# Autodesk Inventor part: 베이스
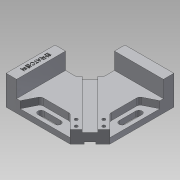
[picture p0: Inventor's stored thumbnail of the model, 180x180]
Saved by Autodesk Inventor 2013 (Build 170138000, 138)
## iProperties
Created: 2019-04
Part Number: 베이스
Material: 알루미늄 6061
Document SubType Name: Modeling
Designer: Administrator
Mass: 603.735 g
Surface Area: 426.536 cm^2
Volume: 222.78 cm^3
Density: 2.71 g/cm^3
Author: Administrator
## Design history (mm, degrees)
sketch "스케치1"
  geometry: L1 (60, -60)-(-60, -60); L2 (-60, -60)-(-60, 60); L3 (-60, 60)-(60, 60); L4 (60, 60)-(60, -60); L5 (60, -60)-(-60, 60); L6 (-60, -60)-(60, 60); 1 further point
  constraints: 12 end point, 2 midpoint, 2 parallel, 1 horizontal, 1 perpendicular
  dimensions: "d0" = 120 distance of L2.end L3.end; "d1" = 120 distance of L1.end L2.end
extrude "돌출1" new body sketch "스케치1" stored distance "d2" = 42; taper "d3" = 0 deg
sketch "스케치2"
  geometry: L1 (-60, -60)-(60, -60) reference; L2 (60, -60)-(60, 60) reference; L3 (60, 60)-(-60, 60) reference; L4 (-60, 60)-(-60, -60) reference; L5 (-45, 45)-(60, 45); L6 (-45, -60)-(-45, 45); L7 (-45, -60)-(60, -60); L8 (60, 45)-(60, -60); 1 further point
  constraints: 8 end point, 2 point on line, 1 horizontal, 1 vertical
  dimensions: "d4" = 15 distance between parallel lines of L3 L5; "d5" = 15 distance between parallel lines of L6 L4
extrude "돌출2" cut sketch "스케치2" distance "d6" = 24; taper "d7" = 0 deg
sketch "스케치3"
  geometry: L1 (60, -60)-(-45, -60) reference; L2 (60, 45)-(60, -60) reference; L3 (31.716, -60)-(60, -31.716); L4 (-45, 45)-(60, -60); 2 further points
  constraints: 4 end point, 3 point on line, 1 midpoint
  dimensions: "d23" = 40 distance of L3.start L3.end
extrude "돌출3" cut sketch "스케치3" distance "d10" = 24; taper "d11" = 0 deg
sketch "스케치5"
  geometry: L1 (60, 60)-(-60, 60) reference; L2 (-60, 60)-(-60, -60) reference; L3 (-60, 10)-(-29.806, 10); L4 (-29.806, 10)-(-10, 29.806); L5 (-10, 29.806)-(-10, 60); L6 (-60, 10)-(-60, 60); L7 (-10, 60)-(-60, 60); L8 (31.716, -60)-(60, -31.716) reference; 1 further point
  constraints: 10 end point, 2 horizontal, 2 point on line, 2 vertical
  dimensions: "d15" = 50 distance between parallel lines of L5 L2; "d16" = 50 distance between parallel lines of L3 L1; "d24" = 93 distance between parallel lines of L8 L4
extrude "돌출4" cut sketch "스케치5" distance "d17" = 42; taper "d18" = 0 deg
sketch "스케치6"
  geometry: L1 (-10, 29.806)-(-29.806, 10) reference; L2 (-25.56, 14.246)-(40.201, -51.515); L3 (-14.246, 25.56)-(51.515, -40.201); L4 (0, 0)-(45.858, -45.858); L5 (-25.56, 14.246)-(-14.246, 25.56); L6 (40.201, -51.515)-(51.515, -40.201); L7 (31.716, -60)-(60, -31.716) reference; 1 further point
  constraints: 10 end point, 3 midpoint, 2 collinear, 2 point on line, 1 other
  dimensions: "d19" = 16 distance between parallel lines of L3 L2
extrude "돌출5" cut sketch "스케치6" distance "d20" = 3.5; taper "d21" = 0 deg
sketch "스케치8"
  geometry: L1 (40.201, -51.515)-(-25.56, 14.246) reference; L2 (31.716, -60)-(-45, -60) reference; L3 (-14.246, 25.56)-(51.515, -40.201) reference; L4 (51.515, -40.201)-(60, -31.716) reference; L5 (60, 45)-(60, -31.716) reference; L6 (-10, 45)-(60, 45) reference; L7 (-10, 45)-(-10, 29.806) reference; L8 (-10, 29.806)-(-14.246, 25.56) reference; L9 (31.716, -60)-(11.716, -40); L10 (11.716, -40)-(-30, -40); L11 (-30, -40)-(-40, -60); L12 (-60, 10)-(-60, -60) reference; 1 further point
  constraints: 6 end point, 1 horizontal, 1 parallel, 1 point on line
  dimensions: "d28" = 20 distance between parallel lines of L2 L10; "d29" = 20 distance from line of L12 L11.end; "d30" = 30 distance from line of L12 L10.end
extrude "돌출6" cut sketch "스케치8" distance "d31" = 10; taper "d32" = 0 deg
sketch "스케치9"
  geometry: L1 (-14.246, 25.56)-(51.515, -40.201) reference; L2 (60, 45)-(60, -31.716) reference; L3 (60, 40)-(40, 30); L4 (40, 30)-(40, -11.716); L5 (40, -11.716)-(60, -31.716); L6 (60, 60)-(-10, 60) reference; L7 (60, 40)-(60, -31.716); 1 further point
  constraints: 8 end point, 2 vertical, 1 parallel, 1 point on line
  dimensions: "d33" = 20 distance between parallel lines of L2 L4; "d34" = 20 distance from line of L6 L3.start; "d35" = 30 distance from line of L6 L3.end
extrude "돌출7" cut sketch "스케치9" distance "d36" = 10; taper "d37" = 0 deg
sketch "스케치10"
  geometry: L1 (31.716, -60)-(-40, -60) reference; L2 (-20, -45.5)-(4, -45.5); L3 (-20, -54.5)-(4, -54.5); L4 (-60, 10)-(-60, -60) reference; A1 r 4.5 centre (-20, -50) between (-20, -45.5) and (-20, -54.5); A2 r 4.5 centre (4, -50) between (4, -45.5) and (4, -54.5); 1 further point
  constraints: 4 end point, 4 point on circle, 4 tangent, 2 centre point, 1 equal radius, 1 horizontal alignment
  dimensions: "d38" = 9 diameter of A2; "d41" = 10 distance from line of L1 A1.centre; "d42" = 40 distance from line of A1.centre L4; "d43" = 24 distance of A2.centre A1.centre
extrude "돌출8" cut sketch "스케치10" distance "d44" = 10; taper "d45" = 0 deg
sketch "스케치11"
  geometry: L1 (60, 40)-(60, -31.716) reference; L2 (45.5, -4)-(45.5, 20); L3 (54.5, -4)-(54.5, 20); L4 (60, 60)-(-10, 60) reference; A1 r 4.5 centre (50, -4) between (45.5, -4) and (54.5, -4); A2 r 4.5 centre (50, 20) between (45.5, 20) and (54.5, 20); 1 further point
  constraints: 4 end point, 4 point on circle, 4 tangent, 2 centre point, 1 equal radius, 1 vertical alignment
  dimensions: "d46" = 9 diameter of A1; "d48" = 10 distance from line of L1 A2.centre; "d49" = 40 distance from line of L4 A2.centre; "d50" = 24 distance of A2.centre A1.centre
extrude "돌출9" cut sketch "스케치11" distance "d51" = 10; taper "d52" = 0 deg
sketch "스케치12"
  geometry: L1 (-60, -31.716)-(-31.716, -60) reference; L2 (29.806, 10)-(10, 29.806) reference; L3 (15.66, 24.146)-(-50.101, -41.615); L4 (24.146, 15.66)-(-41.615, -50.101); L5 (0, 0)-(-45.858, -45.858); L6 (15.66, 24.146)-(24.146, 15.66); L7 (-50.101, -41.615)-(-41.615, -50.101)
  constraints: 10 end point, 4 point on line, 2 collinear, 1 midpoint, 1 perpendicular, 1 other
  dimensions: "d53" = 12 distance between parallel lines of L4 L3
extrude "돌출10" cut sketch "스케치12" distance "d55" = 3; taper "d56" = 0 deg
sketch "스케치13"
  geometry: L1 (-60, -31.716)-(-50.101, -41.615) reference; L2 (-41.615, -50.101)-(-50.101, -41.615) reference; L3 (-45.858, -45.858)-(0, 0); L4 (-51.515, -31.716)-(-31.716, -51.515); 3 further points
  constraints: 4 end point, 2 midpoint, 1 parallel, 1 perpendicular, 1 point on line
  dimensions: "d57" = 28 distance of L4.end L4.start; "d59" = 6 distance from line of L4.start L1; "d61" = 12 distance of point (-43.029, -23.23) L4.start; "d62" = 14 distance from line of L3 point (-43.029, -23.23); "d63" = 12 distance of L4.end point (-23.23, -43.029); "d64" = 14 distance from line of point (-23.23, -43.029) L3
hole "구멍1" sketch "스케치13" at (-51.515, -31.716), (-43.029, -23.23), (-31.716, -51.515), (-23.23, -43.029) diameter "d65" = 4.5; stored, may be unused: countersink angle "d69" = 90 deg, drill point angle "d71" = 118 deg; dims "d66" = 6, "d67" = 8, "d68" = 10, "d70" = 8
fillet "모깎기1" dims "d72" = 5
sketch "스케치14"
  geometry: L1 (-45, 10)-(-60, 10) reference; L2 (-60, 10)-(-60, -60) reference; 2 further points
  constraints: 1 other
  dimensions: "d73" = 35 distance from line of point (-52.5, -25) L1; "d74" = 7.5 distance from line of L2 point (-52.5, -25)
feature "엠보싱1" sketch "스케치14" dims "d0" = 120, "d1" = 120, "d75" = 0.5, "d76" = 0
node "솔리드1"
node "투영된 루프1"
